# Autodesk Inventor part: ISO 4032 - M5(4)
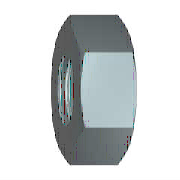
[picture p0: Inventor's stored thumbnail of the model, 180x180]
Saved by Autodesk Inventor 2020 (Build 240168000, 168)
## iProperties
Created: 2019-01
Part Number: ISO 4032 - M5(4)
Material: Nerezová ocel 440C
Description: Šestihranné matice, styl 1 – výrobní řada A a B
Document SubType Name: Modeling
Standard: ISO 4032
Designer: doma
Standard Revision: Fourth edition 2012-12-15
Standards Organization: ISO
Language: cs-CZ
Size Designation: M5
Categories: <MemberInstance><Categories><Category DisplayName="Spojovací materiál" InternalName="e4da775c-781d-43d5-af7c-5136215cf5a6" Mnemonic="FSTN"><Category DisplayName
Density: 7.75 g/cm^3
Appearance: Pololeštěná
IsCustomPart: 0
Author: doma
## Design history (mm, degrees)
sketch "Náčrt1"
  geometry: L1 (-4.619, 0)-(-2.309, 4); L2 (-2.309, 4)-(2.309, 4); L3 (2.309, 4)-(4.619, 0); L4 (4.619, 0)-(2.309, -4); L5 (2.309, -4)-(-2.309, -4); L6 (-2.309, -4)-(-4.619, 0); 2 further points
  constraints: 12 end point, 1 coincident, 1 horizontal, 11 other
  dimensions: "d0" = 9.2376 distance of L3.end L1.start (= 1.1547 x SW)
extrude "Těleso" new body sketch "Náčrt1" distance "d1" = 4.7 (= KOH); taper "d2" = 0 deg
sketch "Náčrt2"
  geometry: L1 (0, 2.309)-(0, 4.619) reference; L2 (0, 4.619)-(4.7, 4.619) reference; L3 (4.7, 2.309)-(4.7, 4.619) reference; L4 (-0.94, 0)-(5.64, 0) reference; L5 (0.675, 4.619)-(0, 3.45); L6 (4.025, 4.619)-(4.7, 3.45)
  constraints: 4 end point, 4 point on line
  dimensions: "d3" = 30 deg angle of L1 L5 (= ANG1); "d4" = 30 deg angle of L3 L6 (= ANG2); "d5" = 6.9 diameter of L5.end L4 (= SW0); "d6" = 6.9 diameter of L6.end L4 (= SW01)
revolve "Zkosení1" sketch "Náčrt2" stored, may be unused: angle "d7" = 90 deg
sketch "Náčrt3"
  geometry: 4 further points
  constraints: 1 coincident, 1 other
hole "Závit" sketch "Náčrt3" at (0, 0) diameter "d25" = 4.134; stored, may be unused: countersink angle "d29" = 82 deg, drill point angle "d31" = 118 deg; dims "d26" = 6, "d27" = 4, "d28" = 2, "d30" = 8
workaxis "Work Axis1"
workplane "Work Plane1"
body "Solid1"
chamfer "Zkosení2" distance "d8" = 0.43301 (= -0.5 x GD1 + 0.5 x NND); stored, may be unused: angle "d9" = 30 deg, second distance "d40" = 0.43301 (= -0.5 x GD1 + 0.5 x NND)
chamfer "Zkosení3" distance "d10" = 0.43301 (= -0.5 x GD1 + 0.5 x NND); stored, may be unused: angle "d11" = 30 deg, second distance "d41" = 0.43301 (= -0.5 x GD1 + 0.5 x NND)
other parameters: "ANG1" = 30 deg [user parameter; used in 1 equation term], "ANG2" = 30 deg [user parameter; used in 1 equation term], "NND" = 5 [user parameter; used in 4 equation terms], "KOH" = 4.7 [user parameter; used in 1 equation term], "SW" = 8 [user parameter; used in 2 equation terms], "SW0" = 6.9 [user parameter; used in 2 equation terms], "SW01" = 6.9 (= SW0) [user parameter; used in 1 equation term], "GD1" = 4.13397 (computed from THREADDIA, PTC, TOA) [user parameter; used in 4 equation terms], "d13" = 0, "d14" = 0, "d39" = 0, "d42" = 0, "GUL" = 0.43301 (= 0.541266 x PTC) [user parameter], "TPU" = 12.5 (computed from PTC) [user parameter], "THREADDIA" = 5 [user parameter; used in 1 equation term], "TOA" = 30 deg [user parameter; used in 1 equation term], "PTC" = 0.8 [user parameter; used in 4 equation terms], "E0" = 9.24 (= 1.155 x SW) [user parameter], "GAL" = 0.43301 (= 0.541266 x PTC) [user parameter]
